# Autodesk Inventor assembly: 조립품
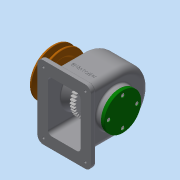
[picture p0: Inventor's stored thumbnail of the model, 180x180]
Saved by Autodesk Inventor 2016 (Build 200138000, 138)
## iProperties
Created: 2018-11
Part Number: 조립품
Material: 일반
Document SubType Name: Assembly
Designer: user
Author: user
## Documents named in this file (14)
- C:\Users\user\Desktop\481111V1003\조립품.iam
- C:\Users\user\Desktop\481111V1003\V-벨트풀리.ipt
- C:\Users\user\Desktop\481111V1003\뒤커버.ipt
- C:\Users\user\Desktop\481111V1003\멈춤나사 M4.ipt
- C:\Users\user\Desktop\481111V1003\베어링 6203.ipt
- C:\Users\user\Desktop\481111V1003\본체.ipt
- C:\Users\user\Desktop\481111V1003\볼트 M4.ipt
- C:\Users\user\Desktop\481111V1003\부시.ipt
- C:\Users\user\Desktop\481111V1003\스퍼기어.ipt
- C:\Users\user\Desktop\481111V1003\앞커버.ipt
- C:\Users\user\Desktop\481111V1003\오일 실 28 40 8.ipt
- C:\Users\user\Desktop\481111V1003\축.ipt
- C:\Users\user\Desktop\481111V1003\키 5x5x18.ipt
- C:\Users\user\Desktop\481111V1003\키 6x6x22.ipt
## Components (1 placed, 1 different names)
1. V-벨트풀리:1
